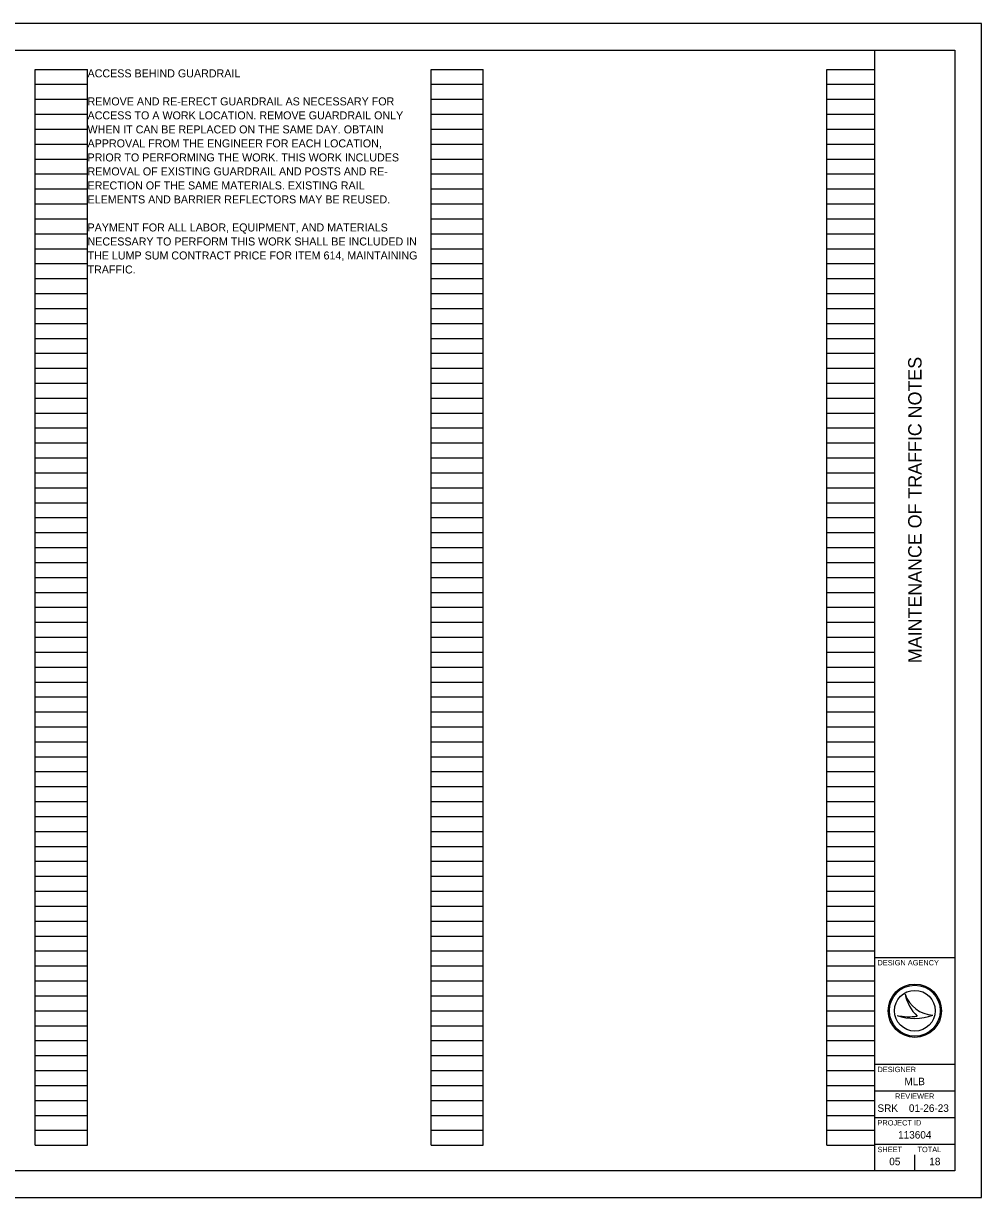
# Model space of a CAD drawing. Extents: x -7 to 34, y 0 to 22.
# Drawn here: x 16.04 to 34, y 0 to 22 of the extents above; entities that cross this region are included whole.
import ezdxf

# ---------------------------------------------------------------- set-up
doc = ezdxf.new("R2010")
doc.units = 0
for name, color, linetype in [('SH_Border', 7, 'Continuous'), ('SH_Cut_Line', 7, 'Continuous'), ('SH_Data', 7, 'Continuous'), ('SH_Text', 7, 'Continuous')]:
    doc.layers.add(name, color=color, linetype=linetype)

msp = doc.modelspace()

# ---------------------------------------------------------------- linework, layer by layer
at = {"layer": 'SH_Border'}
for p, q in [((32, 0.5), (32, 21.5)), ((32, 4.5), (33.5, 4.5)), ((32, 2.5), (33.5, 2.5)), ((32, 2), (33.5, 2)), ((32, 1.5), (33.5, 1.5)), ((32, 1), (33.5, 1))]:
    msp.add_line(p, q, dxfattribs=at)
msp.add_lwpolyline([(1.5, 21.5), (33.5, 21.5), (33.5, 0.5), (1.5, 0.5)], close=True, dxfattribs=at)
at = {"layer": 'SH_Cut_Line'}
msp.add_lwpolyline([(0, 0), (34, 0), (34, 22), (0, 22)], close=True, dxfattribs=at)
at = {"layer": 'SH_Data'}
for p, q in [((16.26, 0.98), (16.26, 21.14)), ((16.26, 21.14), (17.24, 21.14)), ((17.24, 0.98), (17.24, 21.14)), ((23.68, 0.98), (23.68, 21.14)), ((23.68, 21.14), (24.66, 21.14)), ((24.66, 0.98), (24.66, 21.14)), ((31.1, 0.98), (31.1, 21.14)), ((31.1, 21.14), (32, 21.14)), ((32, 0.98), (32, 21.14)), ((16.26, 20.86), (17.24, 20.86)), ((23.68, 20.86), (24.66, 20.86)), ((31.1, 20.86), (32, 20.86)), ((16.26, 20.58), (17.24, 20.58)), ((23.68, 20.58), (24.66, 20.58)), ((31.1, 20.58), (32, 20.58)), ((16.26, 20.3), (17.24, 20.3)), ((23.68, 20.3), (24.66, 20.3)), ((31.1, 20.3), (32, 20.3)), ((16.26, 20.02), (17.24, 20.02)), ((23.68, 20.02), (24.66, 20.02)), ((31.1, 20.02), (32, 20.02)), ((16.26, 19.74), (17.24, 19.74)), ((23.68, 19.74), (24.66, 19.74)), ((31.1, 19.74), (32, 19.74)), ((16.26, 19.46), (17.24, 19.46)), ((23.68, 19.46), (24.66, 19.46)), ((31.1, 19.46), (32, 19.46)), ((16.26, 19.18), (17.24, 19.18)), ((23.68, 19.18), (24.66, 19.18)), ((31.1, 19.18), (32, 19.18)), ((16.26, 18.9), (17.24, 18.9)), ((23.68, 18.9), (24.66, 18.9)), ((31.1, 18.9), (32, 18.9)), ((16.26, 18.62), (17.24, 18.62)), ((23.68, 18.62), (24.66, 18.62)), ((31.1, 18.62), (32, 18.62)), ((16.26, 18.34), (17.24, 18.34)), ((23.68, 18.34), (24.66, 18.34)), ((31.1, 18.34), (32, 18.34)), ((16.26, 18.06), (17.24, 18.06)), ((23.68, 18.06), (24.66, 18.06)), ((31.1, 18.06), (32, 18.06)), ((16.26, 17.78), (17.24, 17.78)), ((23.68, 17.78), (24.66, 17.78)), ((31.1, 17.78), (32, 17.78)), ((16.26, 17.5), (17.24, 17.5)), ((23.68, 17.5), (24.66, 17.5)), ((31.1, 17.5), (32, 17.5)), ((16.26, 17.22), (17.24, 17.22)), ((23.68, 17.22), (24.66, 17.22)), ((31.1, 17.22), (32, 17.22)), ((16.26, 16.94), (17.24, 16.94)), ((23.68, 16.94), (24.66, 16.94)), ((31.1, 16.94), (32, 16.94)), ((16.26, 16.66), (17.24, 16.66)), ((23.68, 16.66), (24.66, 16.66)), ((31.1, 16.66), (32, 16.66)), ((16.26, 16.38), (17.24, 16.38)), ((23.68, 16.38), (24.66, 16.38)), ((31.1, 16.38), (32, 16.38)), ((16.26, 16.1), (17.24, 16.1)), ((23.68, 16.1), (24.66, 16.1)), ((31.1, 16.1), (32, 16.1)), ((16.26, 15.82), (17.24, 15.82)), ((23.68, 15.82), (24.66, 15.82)), ((31.1, 15.82), (32, 15.82)), ((16.26, 15.54), (17.24, 15.54)), ((23.68, 15.54), (24.66, 15.54)), ((31.1, 15.54), (32, 15.54)), ((16.26, 15.26), (17.24, 15.26)), ((23.68, 15.26), (24.66, 15.26)), ((31.1, 15.26), (32, 15.26)), ((16.26, 14.98), (17.24, 14.98)), ((23.68, 14.98), (24.66, 14.98)), ((31.1, 14.98), (32, 14.98)), ((16.26, 14.7), (17.24, 14.7)), ((23.68, 14.7), (24.66, 14.7)), ((31.1, 14.7), (32, 14.7)), ((16.26, 14.42), (17.24, 14.42)), ((23.68, 14.42), (24.66, 14.42)), ((31.1, 14.42), (32, 14.42)), ((16.26, 14.14), (17.24, 14.14)), ((23.68, 14.14), (24.66, 14.14)), ((31.1, 14.14), (32, 14.14)), ((16.26, 13.86), (17.24, 13.86)), ((23.68, 13.86), (24.66, 13.86)), ((31.1, 13.86), (32, 13.86)), ((16.26, 13.58), (17.24, 13.58)), ((23.68, 13.58), (24.66, 13.58)), ((31.1, 13.58), (32, 13.58)), ((16.26, 13.3), (17.24, 13.3)), ((23.68, 13.3), (24.66, 13.3)), ((31.1, 13.3), (32, 13.3)), ((16.26, 13.02), (17.24, 13.02)), ((23.68, 13.02), (24.66, 13.02)), ((31.1, 13.02), (32, 13.02)), ((16.26, 12.74), (17.24, 12.74)), ((23.68, 12.74), (24.66, 12.74)), ((31.1, 12.74), (32, 12.74)), ((16.26, 12.46), (17.24, 12.46)), ((23.68, 12.46), (24.66, 12.46)), ((31.1, 12.46), (32, 12.46)), ((16.26, 12.18), (17.24, 12.18)), ((23.68, 12.18), (24.66, 12.18)), ((31.1, 12.18), (32, 12.18)), ((16.26, 11.9), (17.24, 11.9)), ((23.68, 11.9), (24.66, 11.9)), ((31.1, 11.9), (32, 11.9)), ((16.26, 11.62), (17.24, 11.62)), ((23.68, 11.62), (24.66, 11.62)), ((31.1, 11.62), (32, 11.62)), ((16.26, 11.34), (17.24, 11.34)), ((23.68, 11.34), (24.66, 11.34)), ((31.1, 11.34), (32, 11.34)), ((16.26, 11.06), (17.24, 11.06)), ((23.68, 11.06), (24.66, 11.06)), ((31.1, 11.06), (32, 11.06)), ((16.26, 10.78), (17.24, 10.78)), ((23.68, 10.78), (24.66, 10.78)), ((31.1, 10.78), (32, 10.78)), ((16.26, 10.5), (17.24, 10.5)), ((23.68, 10.5), (24.66, 10.5)), ((31.1, 10.5), (32, 10.5)), ((16.26, 10.22), (17.24, 10.22)), ((23.68, 10.22), (24.66, 10.22)), ((31.1, 10.22), (32, 10.22)), ((16.26, 9.94), (17.24, 9.94)), ((23.68, 9.94), (24.66, 9.94)), ((31.1, 9.94), (32, 9.94)), ((16.26, 9.66), (17.24, 9.66)), ((23.68, 9.66), (24.66, 9.66)), ((31.1, 9.66), (32, 9.66)), ((16.26, 9.38), (17.24, 9.38)), ((23.68, 9.38), (24.66, 9.38)), ((31.1, 9.38), (32, 9.38)), ((16.26, 9.1), (17.24, 9.1)), ((23.68, 9.1), (24.66, 9.1)), ((31.1, 9.1), (32, 9.1)), ((16.26, 8.82), (17.24, 8.82)), ((23.68, 8.82), (24.66, 8.82)), ((31.1, 8.82), (32, 8.82)), ((16.26, 8.54), (17.24, 8.54)), ((23.68, 8.54), (24.66, 8.54)), ((31.1, 8.54), (32, 8.54)), ((16.26, 8.26), (17.24, 8.26)), ((23.68, 8.26), (24.66, 8.26)), ((31.1, 8.26), (32, 8.26)), ((16.26, 7.98), (17.24, 7.98)), ((23.68, 7.98), (24.66, 7.98)), ((31.1, 7.98), (32, 7.98)), ((16.26, 7.7), (17.24, 7.7)), ((23.68, 7.7), (24.66, 7.7)), ((31.1, 7.7), (32, 7.7)), ((16.26, 7.42), (17.24, 7.42)), ((23.68, 7.42), (24.66, 7.42)), ((31.1, 7.42), (32, 7.42)), ((16.26, 7.14), (17.24, 7.14)), ((23.68, 7.14), (24.66, 7.14)), ((31.1, 7.14), (32, 7.14)), ((16.26, 6.86), (17.24, 6.86)), ((23.68, 6.86), (24.66, 6.86)), ((31.1, 6.86), (32, 6.86)), ((16.26, 6.58), (17.24, 6.58)), ((23.68, 6.58), (24.66, 6.58)), ((31.1, 6.58), (32, 6.58)), ((16.26, 6.3), (17.24, 6.3)), ((23.68, 6.3), (24.66, 6.3)), ((31.1, 6.3), (32, 6.3)), ((16.26, 6.02), (17.24, 6.02)), ((23.68, 6.02), (24.66, 6.02)), ((31.1, 6.02), (32, 6.02)), ((16.26, 5.74), (17.24, 5.74)), ((23.68, 5.74), (24.66, 5.74)), ((31.1, 5.74), (32, 5.74)), ((16.26, 5.46), (17.24, 5.46)), ((23.68, 5.46), (24.66, 5.46)), ((31.1, 5.46), (32, 5.46)), ((16.26, 5.18), (17.24, 5.18)), ((23.68, 5.18), (24.66, 5.18)), ((31.1, 5.18), (32, 5.18)), ((16.26, 4.9), (17.24, 4.9)), ((23.68, 4.9), (24.66, 4.9)), ((31.1, 4.9), (32, 4.9)), ((16.26, 4.62), (17.24, 4.62)), ((23.68, 4.62), (24.66, 4.62)), ((31.1, 4.62), (32, 4.62)), ((16.26, 4.34), (17.24, 4.34)), ((23.68, 4.34), (24.66, 4.34)), ((31.1, 4.34), (32, 4.34)), ((16.26, 4.06), (17.24, 4.06)), ((23.68, 4.06), (24.66, 4.06)), ((31.1, 4.06), (32, 4.06)), ((16.26, 3.78), (17.24, 3.78)), ((23.68, 3.78), (24.66, 3.78)), ((31.1, 3.78), (32, 3.78)), ((32.567, 3.81), (32.567, 3.81)), ((16.26, 3.5), (17.24, 3.5)), ((23.68, 3.5), (24.66, 3.5)), ((31.1, 3.5), (32, 3.5)), ((32.417, 3.41), (32.417, 3.41)), ((32.75, 3.5), (32.75, 3.5)), ((33.087, 3.419), (33.087, 3.419)), ((16.26, 3.22), (17.24, 3.22)), ((23.68, 3.22), (24.66, 3.22)), ((31.1, 3.22), (32, 3.22)), ((16.26, 2.94), (17.24, 2.94)), ((23.68, 2.94), (24.66, 2.94)), ((31.1, 2.94), (32, 2.94)), ((16.26, 2.66), (17.24, 2.66)), ((23.68, 2.66), (24.66, 2.66)), ((31.1, 2.66), (32, 2.66)), ((16.26, 2.38), (17.24, 2.38)), ((23.68, 2.38), (24.66, 2.38)), ((31.1, 2.38), (32, 2.38)), ((16.26, 2.1), (17.24, 2.1)), ((23.68, 2.1), (24.66, 2.1)), ((31.1, 2.1), (32, 2.1)), ((16.26, 1.82), (17.24, 1.82)), ((23.68, 1.82), (24.66, 1.82)), ((31.1, 1.82), (32, 1.82)), ((16.26, 1.54), (17.24, 1.54)), ((23.68, 1.54), (24.66, 1.54)), ((31.1, 1.54), (32, 1.54)), ((16.26, 1.26), (17.24, 1.26)), ((23.68, 1.26), (24.66, 1.26)), ((31.1, 1.26), (32, 1.26)), ((16.26, 0.98), (17.24, 0.98)), ((23.68, 0.98), (24.66, 0.98)), ((31.1, 0.98), (32, 0.98)), ((32.375, 0.675), (32.375, 0.675)), ((32.75, 0.5), (32.75, 0.8))]:
    msp.add_line(p, q, dxfattribs=at)
for radius in [0.5, 0.477, 0.477, 0.382]:
    msp.add_circle((32.75, 3.5), radius, dxfattribs=at)
for centre, radius, start, end in [((33.116, 3.998), 0.58, 198.9257, 198.9319), ((33.347, 3.97), 0.796, 191.6379, 191.6421), ((33.116, 3.998), 0.58, 198.9319, 267.1657), ((33.347, 3.97), 0.796, 191.6421, 226.0947), ((32.739, 4.37), 1.013, 251.4576, 290.0832), ((32.648, 4.654), 1.266, 259.4964, 259.4995), ((32.739, 4.37), 1.013, 251.4527, 251.4576), ((32.648, 4.654), 1.266, 259.4995, 276.6672)]:
    msp.add_arc(centre, radius, start, end, dxfattribs=at)

# ---------------------------------------------------------------- texts
msp.add_text('MAINTENANCE OF TRAFFIC NOTES', height=0.25, rotation=90, dxfattribs=at).set_placement((32.875, 10.014))
for s, height, p in [('DESIGN AGENCY', 0.1, (32.05, 4.35)), ('DESIGNER', 0.1, (32.05, 2.35)), ('MLB', 0.14, (32.554, 2.105)), ('REVIEWER', 0.1, (32.378, 1.85)), ('SRK', 0.14, (32.049, 1.605)), ('01-26-23', 0.14, (32.638, 1.605)), ('PROJECT ID', 0.1, (32.05, 1.35)), ('113604', 0.14, (32.436, 1.105)), ('SHEET', 0.1, (32.05, 0.85)), ('TOTAL', 0.1, (32.8, 0.85)), ('05', 0.14, (32.27, 0.605)), ('18', 0.14, (33.021, 0.605))]:
    msp.add_text(s, height=height, dxfattribs=at).set_placement(p)
at = {"layer": 'SH_Text'}
for s, p in [('ACCESS BEHIND GUARDRAIL', (17.24, 20.99)), ('REMOVE AND RE-ERECT GUARDRAIL AS NECESSARY FOR ', (17.24, 20.465)), ('ACCESS TO A WORK LOCATION. REMOVE GUARDRAIL ONLY ', (17.24, 20.203)), ('WHEN IT CAN BE REPLACED ON THE SAME DAY. OBTAIN ', (17.24, 19.94)), ('APPROVAL FROM THE ENGINEER FOR EACH LOCATION, ', (17.24, 19.678)), ('PRIOR TO PERFORMING THE WORK. THIS WORK INCLUDES ', (17.24, 19.415)), ('REMOVAL OF EXISTING GUARDRAIL AND POSTS AND RE-', (17.24, 19.153)), ('ERECTION OF THE SAME MATERIALS. EXISTING RAIL ', (17.24, 18.89)), ('ELEMENTS AND BARRIER REFLECTORS MAY BE REUSED.  ', (17.24, 18.628)), ('PAYMENT FOR ALL LABOR, EQUIPMENT, AND MATERIALS ', (17.24, 18.103)), ('NECESSARY TO PERFORM THIS WORK SHALL BE INCLUDED IN ', (17.24, 17.84)), ('THE LUMP SUM CONTRACT PRICE FOR ITEM 614, MAINTAINING ', (17.24, 17.578)), ('TRAFFIC.', (17.24, 17.315))]:
    msp.add_text(s, height=0.15, dxfattribs=at).set_placement(p)

doc.saveas('drawing.dxf')
